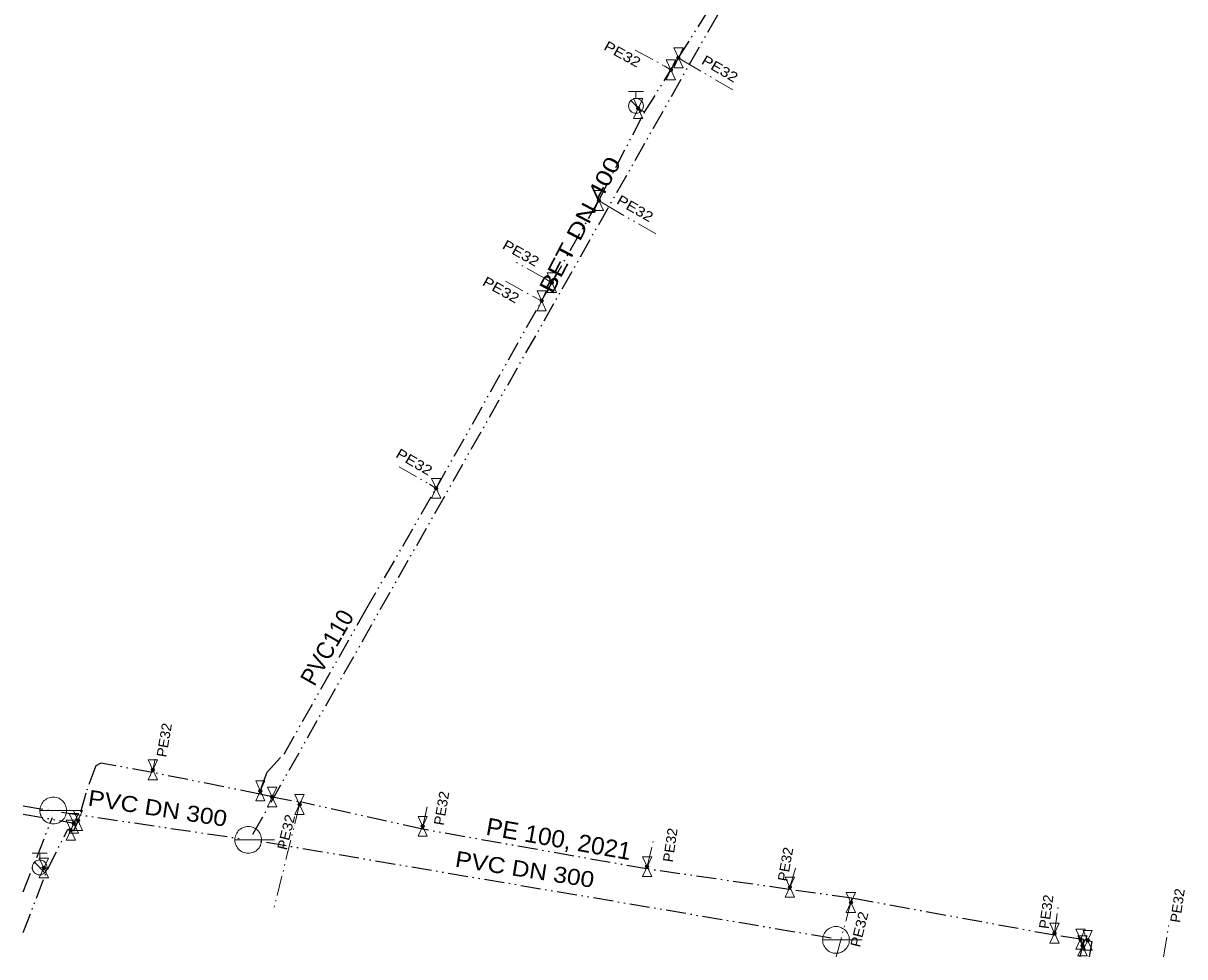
# Model space of a CAD drawing. Extents: x -600643 to -600531, y -1081783 to -1081649.
# Drawn here: x -600643.3 to -600555.7, y -1081783.3 to -1081713 of the extents above; entities that cross this region are included whole.
import ezdxf
from ezdxf.enums import TextEntityAlignment as Align

# ---------------------------------------------------------------- set-up
doc = ezdxf.new("R2010")
doc.units = 0
doc.header["$LTSCALE"] = 0.3
doc.linetypes.add('DASH_DOUBLE_DOT', pattern=[9.2, 5, -1.2, 0.3, -1.2, 0.3, -1.2])
for name, color, linetype, lineweight in [('1', 7, 'DASH_DOUBLE_DOT', 25), ('10', 7, 'Continuous', 13), ('55', 7, 'DASH_DOUBLE_DOT', 25), ('57', 7, 'Continuous', 13), ('58', 7, 'DASH_DOUBLE_DOT', 13), ('59', 7, 'Continuous', 13), ('9', 7, 'DASH_DOUBLE_DOT', 25)]:
    doc.layers.add(name, color=color, linetype=linetype, lineweight=lineweight)
for name, color, linetype in [('11', 7, 'Continuous'), ('3', 7, 'Continuous'), ('56', 7, 'Continuous')]:
    doc.layers.add(name, color=color, linetype=linetype)

msp = doc.modelspace()

# ---------------------------------------------------------------- hatches: boundary and pattern name
at = {"layer": '57'}
for points in [[(-600593.7778, -1081715.57, 1), (-600594.0422, -1081715.57, 1)], [(-600594.3378, -1081716.47, 1), (-600594.6022, -1081716.47, 1)], [(-600596.8048, -1081719.377, 1), (-600597.0692, -1081719.377, 1)], [(-600599.7778, -1081726.31, 1), (-600600.0422, -1081726.31, 1)], [(-600603.3178, -1081732.51, 1), (-600603.5822, -1081732.51, 1)], [(-600604.0878, -1081733.88, 1), (-600604.3522, -1081733.88, 1)], [(-600612.0378, -1081748.01, 1), (-600612.3022, -1081748.01, 1)], [(-600633.4078, -1081769.22, 1), (-600633.6722, -1081769.22, 1)], [(-600625.2978, -1081770.8, 1), (-600625.5622, -1081770.8, 1)], [(-600624.4178, -1081771.27, 1), (-600624.6822, -1081771.27, 1)], [(-600622.3378, -1081771.83, 1), (-600622.6022, -1081771.83, 1)], [(-600639.5978, -1081773.77, 1), (-600639.8622, -1081773.77, 1)], [(-600639.3708, -1081773.252, 1), (-600639.6352, -1081773.252, 1)], [(-600639.0478, -1081773.05, 1), (-600639.3122, -1081773.05, 1)], [(-600613.0578, -1081773.48, 1), (-600613.3222, -1081773.48, 1)], [(-600641.6178, -1081776.62, 1), (-600641.8822, -1081776.62, 1)], [(-600596.1378, -1081776.52, 1), (-600596.4022, -1081776.52, 1)], [(-600585.3678, -1081778.06, 1), (-600585.6322, -1081778.06, 1)], [(-600580.7678, -1081779.22, 1), (-600581.0322, -1081779.22, 1)], [(-600565.4178, -1081781.53, 1), (-600565.6822, -1081781.53, 1)], [(-600563.4578, -1081781.98, 1), (-600563.7222, -1081781.98, 1)], [(-600563.3078, -1081782.48, 1), (-600563.5722, -1081782.48, 1)], [(-600562.9168, -1081782.069, 1), (-600563.1812, -1081782.069, 1)]]:
    msp.add_hatch(color=256, dxfattribs=at).paths.add_polyline_path(points)

# ---------------------------------------------------------------- linework, layer by layer
at = {"layer": '1'}
msp.add_line((-600625.993, -1081774.075), (-600579.207, -1081691.645), dxfattribs=at)
at = {"layer": '10'}
for p, q in [((-600642.054, -1081772.29), (-600639.078, -1081772.29)), ((-600627.351, -1081774.504), (-600624.375, -1081774.504)), ((-600583.034, -1081782.042), (-600580.058, -1081782.042))]:
    msp.add_line(p, q, dxfattribs=at)
for points in [[(-600641.046, -1081771.282), (-600641.151, -1081771.288), (-600641.255, -1081771.304), (-600641.357, -1081771.332), (-600641.456, -1081771.37), (-600641.55, -1081771.417), (-600641.638, -1081771.475), (-600641.72, -1081771.541), (-600641.795, -1081771.616), (-600641.861, -1081771.698), (-600641.919, -1081771.786), (-600641.966, -1081771.88), (-600642.004, -1081771.979), (-600642.032, -1081772.081), (-600642.048, -1081772.185), (-600642.054, -1081772.29), (-600642.048, -1081772.395), (-600642.032, -1081772.5), (-600642.004, -1081772.602), (-600641.966, -1081772.7), (-600641.919, -1081772.794), (-600641.861, -1081772.883), (-600641.795, -1081772.965), (-600641.72, -1081773.039), (-600641.638, -1081773.105), (-600641.55, -1081773.163), (-600641.456, -1081773.211), (-600641.357, -1081773.249), (-600641.255, -1081773.276), (-600641.151, -1081773.292), (-600641.046, -1081773.298), (-600640.941, -1081773.292), (-600640.836, -1081773.276), (-600640.734, -1081773.249), (-600640.636, -1081773.211), (-600640.542, -1081773.163), (-600640.453, -1081773.105), (-600640.371, -1081773.039), (-600640.297, -1081772.965), (-600640.231, -1081772.883), (-600640.173, -1081772.794), (-600640.125, -1081772.7), (-600640.087, -1081772.602), (-600640.06, -1081772.5), (-600640.044, -1081772.395), (-600640.038, -1081772.29), (-600640.044, -1081772.185), (-600640.06, -1081772.081), (-600640.087, -1081771.979), (-600640.125, -1081771.88), (-600640.173, -1081771.786), (-600640.231, -1081771.698), (-600640.297, -1081771.616), (-600640.371, -1081771.541), (-600640.453, -1081771.475), (-600640.542, -1081771.417), (-600640.636, -1081771.37), (-600640.734, -1081771.332), (-600640.836, -1081771.304), (-600640.941, -1081771.288)], [(-600626.343, -1081773.496), (-600626.448, -1081773.502), (-600626.552, -1081773.518), (-600626.654, -1081773.546), (-600626.753, -1081773.584), (-600626.847, -1081773.631), (-600626.935, -1081773.689), (-600627.017, -1081773.755), (-600627.092, -1081773.83), (-600627.158, -1081773.912), (-600627.216, -1081774), (-600627.263, -1081774.094), (-600627.301, -1081774.193), (-600627.329, -1081774.295), (-600627.345, -1081774.399), (-600627.351, -1081774.504), (-600627.345, -1081774.609), (-600627.329, -1081774.714), (-600627.301, -1081774.816), (-600627.263, -1081774.914), (-600627.216, -1081775.008), (-600627.158, -1081775.097), (-600627.092, -1081775.179), (-600627.017, -1081775.253), (-600626.935, -1081775.319), (-600626.847, -1081775.377), (-600626.753, -1081775.425), (-600626.654, -1081775.463), (-600626.552, -1081775.49), (-600626.448, -1081775.506), (-600626.343, -1081775.512), (-600626.238, -1081775.506), (-600626.133, -1081775.49), (-600626.031, -1081775.463), (-600625.933, -1081775.425), (-600625.839, -1081775.377), (-600625.75, -1081775.319), (-600625.668, -1081775.253), (-600625.594, -1081775.179), (-600625.528, -1081775.097), (-600625.47, -1081775.008), (-600625.422, -1081774.914), (-600625.384, -1081774.816), (-600625.357, -1081774.714), (-600625.341, -1081774.609), (-600625.335, -1081774.504), (-600625.341, -1081774.399), (-600625.357, -1081774.295), (-600625.384, -1081774.193), (-600625.422, -1081774.094), (-600625.47, -1081774), (-600625.528, -1081773.912), (-600625.594, -1081773.83), (-600625.668, -1081773.755), (-600625.75, -1081773.689), (-600625.839, -1081773.631), (-600625.933, -1081773.584), (-600626.031, -1081773.546), (-600626.133, -1081773.518), (-600626.238, -1081773.502)], [(-600582.026, -1081781.034), (-600582.131, -1081781.04), (-600582.235, -1081781.056), (-600582.337, -1081781.084), (-600582.436, -1081781.122), (-600582.53, -1081781.169), (-600582.618, -1081781.227), (-600582.7, -1081781.293), (-600582.775, -1081781.368), (-600582.841, -1081781.45), (-600582.899, -1081781.538), (-600582.946, -1081781.632), (-600582.984, -1081781.731), (-600583.012, -1081781.833), (-600583.028, -1081781.937), (-600583.034, -1081782.042), (-600583.028, -1081782.147), (-600583.012, -1081782.252), (-600582.984, -1081782.354), (-600582.946, -1081782.452), (-600582.899, -1081782.546), (-600582.841, -1081782.635), (-600582.775, -1081782.717), (-600582.7, -1081782.791), (-600582.618, -1081782.857), (-600582.53, -1081782.915), (-600582.436, -1081782.963), (-600582.337, -1081783.001), (-600582.235, -1081783.028), (-600582.131, -1081783.044), (-600582.026, -1081783.05), (-600581.921, -1081783.044), (-600581.816, -1081783.028), (-600581.714, -1081783.001), (-600581.616, -1081782.963), (-600581.522, -1081782.915), (-600581.433, -1081782.857), (-600581.351, -1081782.791), (-600581.277, -1081782.717), (-600581.211, -1081782.635), (-600581.153, -1081782.546), (-600581.105, -1081782.452), (-600581.067, -1081782.354), (-600581.04, -1081782.252), (-600581.024, -1081782.147), (-600581.018, -1081782.042), (-600581.024, -1081781.937), (-600581.04, -1081781.833), (-600581.067, -1081781.731), (-600581.105, -1081781.632), (-600581.153, -1081781.538), (-600581.211, -1081781.45), (-600581.277, -1081781.368), (-600581.351, -1081781.293), (-600581.433, -1081781.227), (-600581.522, -1081781.169), (-600581.616, -1081781.122), (-600581.714, -1081781.084), (-600581.816, -1081781.056), (-600581.921, -1081781.04)]]:
    msp.add_lwpolyline(points, close=True, dxfattribs=at)
at = {"layer": '55'}
for p, q in [((-600596.465, -1081719.667), (-600594.394, -1081716.35)), ((-600599.91, -1081726.31), (-600596.463, -1081719.666)), ((-600612.17, -1081748.01), (-600604.22, -1081733.88)), ((-600625.46, -1081771.06), (-600633.59, -1081769.42)), ((-600624.55, -1081771.27), (-600622.44, -1081771.63)), ((-600613.21, -1081773.7), (-600622.44, -1081771.63)), ((-600643.31, -1081772.554), (-600639.6, -1081773.22)), ((-600641.49, -1081776.74), (-600639.946, -1081773.704)), ((-600639.946, -1081773.704), (-600639.73, -1081773.77)), ((-600639.501, -1081773.252), (-600639.6, -1081773.22)), ((-600639.501, -1081773.252), (-600639.304, -1081773.333)), ((-600596.32, -1081776.69), (-600613.21, -1081773.7)), ((-600643.31, -1081781.487), (-600641.49, -1081776.74)), ((-600585.55, -1081778.24), (-600596.32, -1081776.69)), ((-600580.82, -1081778.9), (-600585.55, -1081778.24)), ((-600565.55, -1081781.69), (-600580.82, -1081778.9)), ((-600563.59, -1081781.98), (-600565.55, -1081781.69)), ((-600563.44, -1081782.48), (-600563.645, -1081783.31)), ((-600563.352, -1081782.017), (-600563.59, -1081781.98)), ((-600563.35, -1081782.02), (-600563.44, -1081782.48))]:
    msp.add_line(p, q, dxfattribs=at)
for points in [[(-600594.47, -1081716.47), (-600593.91, -1081715.57), (-600587.36, -1081705.28), (-600586.52, -1081703.99)], [(-600604.22, -1081733.88), (-600603.45, -1081732.51), (-600599.91, -1081726.31)], [(-600625.43, -1081770.8), (-600625.26, -1081770.33), (-600624.92, -1081769.41), (-600623.62, -1081767.99), (-600617.47, -1081757.17), (-600612.17, -1081748.01)], [(-600633.59, -1081769.42), (-600637.47, -1081768.71), (-600637.83, -1081768.93), (-600638.6, -1081770.97), (-600639.18, -1081773.05), (-600639.515, -1081773.838), (-600639.73, -1081773.77)], [(-600624.55, -1081771.27), (-600625.46, -1081771.06), (-600625.43, -1081770.8)], [(-600563.35, -1081782.02), (-600563.08, -1081782.06), (-600562.74, -1081782.16), (-600562.929, -1081783.31)]]:
    msp.add_lwpolyline(points, dxfattribs=at)
at = {"layer": '57'}
for points in [[(-600594.26, -1081714.82), (-600593.56, -1081714.82), (-600594.26, -1081716.32), (-600593.56, -1081716.32)], [(-600594.82, -1081715.72), (-600594.12, -1081715.72), (-600594.82, -1081717.22), (-600594.12, -1081717.22)], [(-600597.287, -1081718.627), (-600596.587, -1081718.627), (-600597.287, -1081720.127), (-600596.587, -1081720.127)], [(-600600.26, -1081725.56), (-600599.56, -1081725.56), (-600600.26, -1081727.06), (-600599.56, -1081727.06)], [(-600603.8, -1081731.76), (-600603.1, -1081731.76), (-600603.8, -1081733.26), (-600603.1, -1081733.26)], [(-600604.57, -1081733.13), (-600603.87, -1081733.13), (-600604.57, -1081734.63), (-600603.87, -1081734.63)], [(-600612.52, -1081747.26), (-600611.82, -1081747.26), (-600612.52, -1081748.76), (-600611.82, -1081748.76)], [(-600633.89, -1081768.47), (-600633.19, -1081768.47), (-600633.89, -1081769.97), (-600633.19, -1081769.97)], [(-600625.78, -1081770.05), (-600625.08, -1081770.05), (-600625.78, -1081771.55), (-600625.08, -1081771.55)], [(-600624.9, -1081770.52), (-600624.2, -1081770.52), (-600624.9, -1081772.02), (-600624.2, -1081772.02)], [(-600622.82, -1081771.08), (-600622.12, -1081771.08), (-600622.82, -1081772.58), (-600622.12, -1081772.58)], [(-600639.853, -1081772.502), (-600639.153, -1081772.502), (-600639.853, -1081774.002), (-600639.153, -1081774.002)], [(-600639.53, -1081772.3), (-600638.83, -1081772.3), (-600639.53, -1081773.8), (-600638.83, -1081773.8)], [(-600613.54, -1081772.73), (-600612.84, -1081772.73), (-600613.54, -1081774.23), (-600612.84, -1081774.23)], [(-600640.08, -1081773.02), (-600639.38, -1081773.02), (-600640.08, -1081774.52), (-600639.38, -1081774.52)], [(-600642.1, -1081775.87), (-600641.4, -1081775.87), (-600642.1, -1081777.37), (-600641.4, -1081777.37)], [(-600596.62, -1081775.77), (-600595.92, -1081775.77), (-600596.62, -1081777.27), (-600595.92, -1081777.27)], [(-600585.85, -1081777.31), (-600585.15, -1081777.31), (-600585.85, -1081778.81), (-600585.15, -1081778.81)], [(-600581.25, -1081778.47), (-600580.55, -1081778.47), (-600581.25, -1081779.97), (-600580.55, -1081779.97)], [(-600565.9, -1081780.78), (-600565.2, -1081780.78), (-600565.9, -1081782.28), (-600565.2, -1081782.28)], [(-600563.94, -1081781.23), (-600563.24, -1081781.23), (-600563.94, -1081782.73), (-600563.24, -1081782.73)], [(-600563.399, -1081781.319), (-600562.699, -1081781.319), (-600563.399, -1081782.819), (-600562.699, -1081782.819)], [(-600563.79, -1081781.73), (-600563.09, -1081781.73), (-600563.79, -1081783.23), (-600563.09, -1081783.23)]]:
    msp.add_lwpolyline(points, close=True, dxfattribs=at)
for centre in [(-600593.91, -1081715.57), (-600594.47, -1081716.47), (-600596.937, -1081719.377), (-600599.91, -1081726.31), (-600603.45, -1081732.51), (-600604.22, -1081733.88), (-600612.17, -1081748.01), (-600633.54, -1081769.22), (-600625.43, -1081770.8), (-600624.55, -1081771.27), (-600622.47, -1081771.83), (-600639.73, -1081773.77), (-600639.503, -1081773.252), (-600639.18, -1081773.05), (-600613.19, -1081773.48), (-600641.75, -1081776.62), (-600596.27, -1081776.52), (-600585.5, -1081778.06), (-600580.9, -1081779.22), (-600565.55, -1081781.53), (-600563.59, -1081781.98), (-600563.44, -1081782.48), (-600563.049, -1081782.069)]:
    msp.add_circle(centre, 0.1322, dxfattribs=at)
at = {"layer": '58'}
msp.add_line((-600557.331, -1081783.31), (-600556.945, -1081780.966), dxfattribs=at)
for points in [[(-600597.165, -1081714.983), (-600594.99, -1081716.17), (-600594.47, -1081716.47)], [(-600593.91, -1081715.57), (-600593.51, -1081715.81), (-600589.539, -1081718.134)], [(-600595.606, -1081728.828), (-600599.19, -1081726.77), (-600599.91, -1081726.31)], [(-600603.45, -1081732.51), (-600604.01, -1081732.18), (-600606.146, -1081730.985)], [(-600606.936, -1081732.396), (-600604.91, -1081733.53), (-600604.22, -1081733.88)], [(-600614.964, -1081746.379), (-600612.68, -1081747.7), (-600612.17, -1081748.01)], [(-600633.59, -1081769.42), (-600633.54, -1081769.22), (-600633.372, -1081768.407)], [(-600622.44, -1081771.63), (-600622.47, -1081771.83), (-600624.442, -1081779.804)], [(-600613.21, -1081773.7), (-600613.19, -1081773.48), (-600612.819, -1081771.857)], [(-600596.32, -1081776.69), (-600596.27, -1081776.52), (-600595.817, -1081774.636)], [(-600585.55, -1081778.24), (-600585.5, -1081778.06), (-600584.986, -1081776.327)], [(-600582.009, -1081783.31), (-600580.9, -1081779.22), (-600580.82, -1081778.9)], [(-600565.55, -1081781.69), (-600565.55, -1081781.53), (-600565.26, -1081779.51)]]:
    msp.add_lwpolyline(points, dxfattribs=at)
at = {"layer": '59'}
for p, q in [((-600597.666, -1081718.115), (-600596.548, -1081718.115)), ((-600597.107, -1081718.627), (-600597.107, -1081718.115)), ((-600596.712, -1081719.58), (-600597.502, -1081718.79)), ((-600642.629, -1081775.51), (-600641.511, -1081775.51)), ((-600641.675, -1081776.975), (-600642.465, -1081776.185)), ((-600642.07, -1081776.022), (-600642.07, -1081775.51))]:
    msp.add_line(p, q, dxfattribs=at)
at = {"layer": '59', "linetype": 'DASH_DOUBLE_DOT'}
for points in [[(-600596.463, -1081719.666), (-600596.937, -1081719.377), (-600597.107, -1081719.185)], [(-600642.07, -1081776.58), (-600641.75, -1081776.62), (-600641.49, -1081776.74)]]:
    msp.add_lwpolyline(points, dxfattribs=at)
at = {"layer": '59'}
for centre in [(-600597.107, -1081719.1855), (-600642.07, -1081776.5805)]:
    msp.add_circle(centre, 0.5587, dxfattribs=at)
at = {"layer": '9'}
for p, q in [((-600643.31, -1081771.924), (-600641.413, -1081772.254)), ((-600643.31, -1081778.408), (-600641.101, -1081772.806)), ((-600640.425, -1081772.413), (-600626.735, -1081774.437)), ((-600582.381, -1081781.916), (-600625.611, -1081774.598))]:
    msp.add_line(p, q, dxfattribs=at)

# ---------------------------------------------------------------- texts
at = {"layer": '11', "width": 1.15}
for p in [(-600633.2623, -1081772.7117), (-600605.5793, -1081777.3167)]:
    msp.add_text('PVC DN 300', height=1.2, rotation=351.245, dxfattribs=at).set_placement(p, align=Align.CENTER)
at = {"layer": '3', "width": 1.25}
msp.add_text('BET DN 400', height=1.2, rotation=62.482, dxfattribs=at).set_placement((-600600.8003, -1081728.4217), align=Align.CENTER)
at = {"layer": '56', "width": 0.95}
msp.add_text('PVC110', height=1.3, rotation=60.386, dxfattribs=at).set_placement((-600621.356, -1081762.993))
at = {"layer": '56', "width": 1.05}
msp.add_text('PE 100, 2021', height=1.3, rotation=349.961, dxfattribs=at).set_placement((-600603.0373, -1081775.0667), align=Align.CENTER)
at = {"layer": '58'}
for rotation, width, p in [(331.39, 1.2, (-600599.597, -1081714.912)), (329.661, 1.2, (-600592.24, -1081715.974)), (330.129, 1.2, (-600598.636, -1081726.51)), (330.769, 1.2, (-600607.248, -1081729.896)), (330.769, 1.2, (-600608.75, -1081732.658)), (329.96, 1.2, (-600615.287, -1081745.615)), (80.248, 1.05, (-600632.527, -1081768.314)), (80.156, 1.05, (-600611.618, -1081773.45)), (81.568, 1.05, (-600594.34, -1081776.223)), (79.913, 1.05, (-600585.69, -1081777.671)), (81.925, 1.05, (-600565.983, -1081781.245)), (81.733, 1.05, (-600556.089, -1081780.778))]:
    msp.add_text('PE32', height=0.75, rotation=rotation, dxfattribs=dict(at, width=width)).set_placement(p)
at = {"layer": '58', "width": 1.1}
for rotation, p in [(76.131, (-600623.1192, -1081774.0089)), (75.964, (-600579.8962, -1081781.329))]:
    msp.add_text('PE32', height=0.75, rotation=rotation, dxfattribs=at).set_placement(p, align=Align.CENTER)

doc.saveas('drawing.dxf')
